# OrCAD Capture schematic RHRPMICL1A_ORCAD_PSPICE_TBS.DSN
size Custom
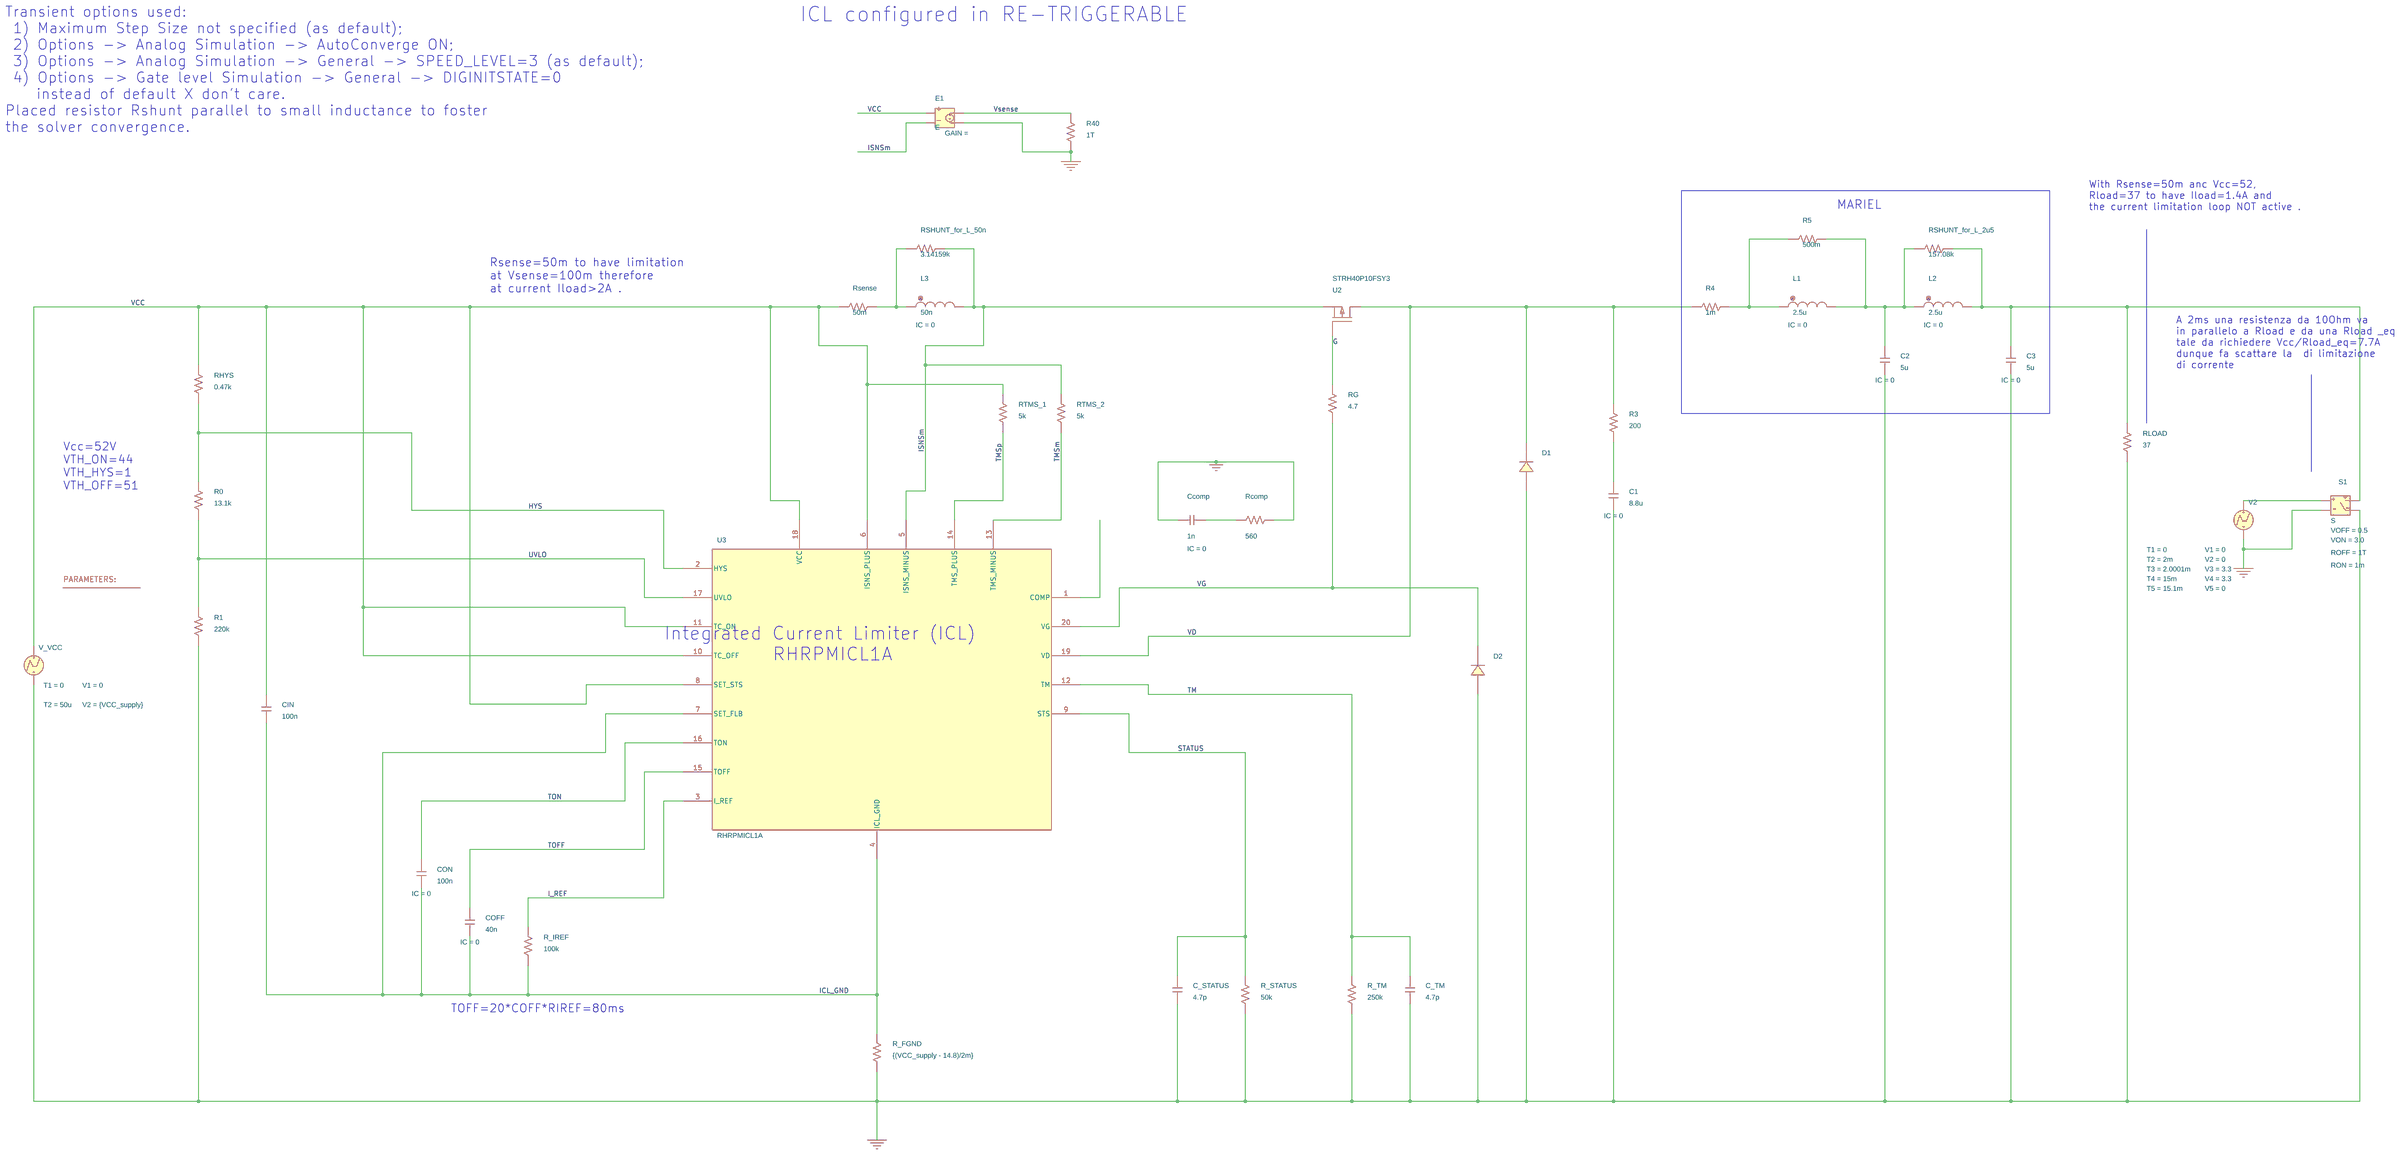
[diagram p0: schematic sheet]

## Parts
1  PARAM
C1  8.8u  [RAD/CK05]
C2  5u  [RAD/CK05]
C3  5u  [RAD/CK05]
C_STATUS  4.7p  [RAD/CK05]
C_TM  4.7p  [RAD/CK05]
Ccomp  1n  [RAD/CK05]
CIN  100n  [RAD/CK05]
COFF  40n  [RAD/CK05]
CON  100n  [RAD/CK05]
D1  STTH310S  [DO41]
D2  STTH310S  [DO41]
E1  E
L1  2.5u  [DISC/.350x.175/LS.200x.100/.034]
L2  2.5u  [DISC/.350x.175/LS.200x.100/.034]
L3  50n  [DISC/.350x.175/LS.200x.100/.034]
R0  13.1k  [AX/RC05]
R1  220k  [AX/RC05]
R3  200  [AX/RC05]
R4  1m  [AX/RC05]
R5  500m  [AX/RC05]
R40  1T  [AX/RC05]
R_FGND  {(VCC_supply - 14.8)/2m}  [AX/RC05]
R_IREF  100k  [AX/RC05]
R_STATUS  50k  [AX/RC05]
R_TM  250k  [AX/RC05]
Rcomp  560  [AX/RC05]
RG  4.7  [AX/RC05]
RHYS  0.47k  [AX/RC05]
RLOAD  37  [AX/RC05]
Rsense  50m  [AX/RC05]
RSHUNT_for_L_2u5  157.08k  [AX/RC05]
RSHUNT_for_L_50n  3.14159k  [AX/RC05]
RTMS_1  5k  [AX/RC05]
RTMS_2  5k  [AX/RC05]
S1  S
U2  STRH40P10FSY3
U3  RHRPMICL1A
V2  VPWL
V_VCC  VPWL

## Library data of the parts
1 = PARAM: VCC_supply: 52
C1-C3 Ccomp COFF CON = C: IC: 0
C_STATUS C_TM CIN = C
D1 D2 = STTH310S
E1 = E
L1-L3 = L: IC: 0
R0 R1 R3-R5 R40 R_FGND R_IREF R_STATUS R_TM Rcomp RG RHYS RLOAD Rsense RSHUNT_for_L_2u5 RSHUNT_for_L_50n RTMS_1 RTMS_2 = R
S1 = S: ROFF: 1T; RON: 1m; VOFF: 0.5; VON: 3.0
U2 = STRH40P10FSY3
U3 = RHRPMICL1A
V2 = VPWL: T1: 0; T2: 2m; T3: 2.0001m; T4: 15m; T5: 15.1m; V1: 0; V2: 0; V3: 3.3; V4: 3.3; V5: 0
V_VCC = VPWL: T1: 0; T2: 50u; V1: 0; V2: {VCC_supply}

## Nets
VCC: CIN.2 E1.1 RHYS.2 Rsense.1 RTMS_1.2 U3.6(ISNS_PLUS) U3.8(SET_STS) U3.10(TC_OFF) U3.11(TC_ON) U3.18(VCC) V_VCC.1(+)
0: C1.1 C2.1 C3.1 C_STATUS.1 C_TM.1 Ccomp.1 D1.2(A) D2.2(A) E1.4 R1.1 R40.1 R_FGND.1 R_STATUS.1 R_TM.1 Rcomp.2 RLOAD.1 S1.1(2) S1.3(4) V2.2(-) V_VCC.2(-)
G: RG.2 U2.2(G)
HYS: R0.2 RHYS.1 U3.2(HYS)
I_REF: R_IREF.2 U3.3(I_REF)
ICL_GND: CIN.1 COFF.1 CON.1 R_FGND.2 R_IREF.1 U3.4(ICL_GND) U3.7(SET_FLB)
ISNSm: E1.2 L3.2 RSHUNT_for_L_50n.2 RTMS_2.2 U2.3(S) U3.5(ISNS_MINUS)
STATUS: C_STATUS.2 R_STATUS.2 U3.9(STS)
TM: C_TM.2 R_TM.2 U3.12(TM)
TMSm: RTMS_2.1 U3.13(TMS_MINUS)
TMSp: RTMS_1.1 U3.14(TMS_PLUS)
TOFF: COFF.2 U3.15(TOFF)
TON: CON.2 U3.16(TON)
UVLO: R0.1 R1.2 U3.17(UVLO)
VD: D1.1(C) R3.2 R4.1 U2.1(D) U3.19(VD)
VG: D2.1(C) RG.1 U3.20(VG)
Vsense: E1.3 R40.2
N16432529: L3.1 Rsense.2 RSHUNT_for_L_50n.1
N16433611: C1.2 R3.1
N16433639: L1.1 R4.2 R5.1
N16433657: C2.2 L1.2 L2.1 R5.2 RSHUNT_for_L_2u5.1
N16433691: C3.2 L2.2 RLOAD.2 RSHUNT_for_L_2u5.2 S1.2(3)
N16434025: S1.0(1) V2.1(+)
N16442011: Ccomp.2 Rcomp.1

Not connected (* = marked no-connect by the designer): U3 1(COMP)

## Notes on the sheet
- Transient options used:
   1) Maximum Step Size not specified (as default);
   2) Options -> Analog Simulation -> AutoConverge ON;
   3) Options -> Analog Simulation -> General -> SPEED_LEVEL=3 (as default);
   4) Options -> Gate level Simulation -> General -> DIGINITSTATE=0
      instead of default X don't care.
  Placed resistor Rshunt parallel to small inductance to foster
  the solver convergence.
- ICL configured in RE-TRIGGERABLE
- With Rsense=50m anc Vcc=52,
  Rload=37 to have Iload=1.4A and
  the current limitation loop NOT active .
- MARIEL
- Rsense=50m to have limitation
  at Vsense=100m therefore
  at current Iload>2A .
- A 2ms una resistenza da 10Ohm va
  in parallelo a Rload e da una Rload _eq
  tale da richiedere Vcc/Rload_eq=7.7A
  dunque fa scattare la  di limitazione
  di corrente
- Vcc=52V
  VTH_ON=44
  VTH_HYS=1
  VTH_OFF=51
- Integrated Current Limiter (ICL)
             RHRPMICL1A
- TOFF=20*COFF*RIREF=80ms
